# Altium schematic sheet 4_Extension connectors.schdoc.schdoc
size 309 x 223 mm; Symbol: Artery_A4; Device: Artery_A4; Company: Artery Technology; Version: 1.1; Page Size: A4; @Project Name: AT-START-F423 V1.1; @Page Count: 4; @Update Date: 2024-04-30; @Create Date: 2023-04-24; @Schematic Name: AT-START-F423 V1.1; @Page No: 4; @Page Name: Extension connectors
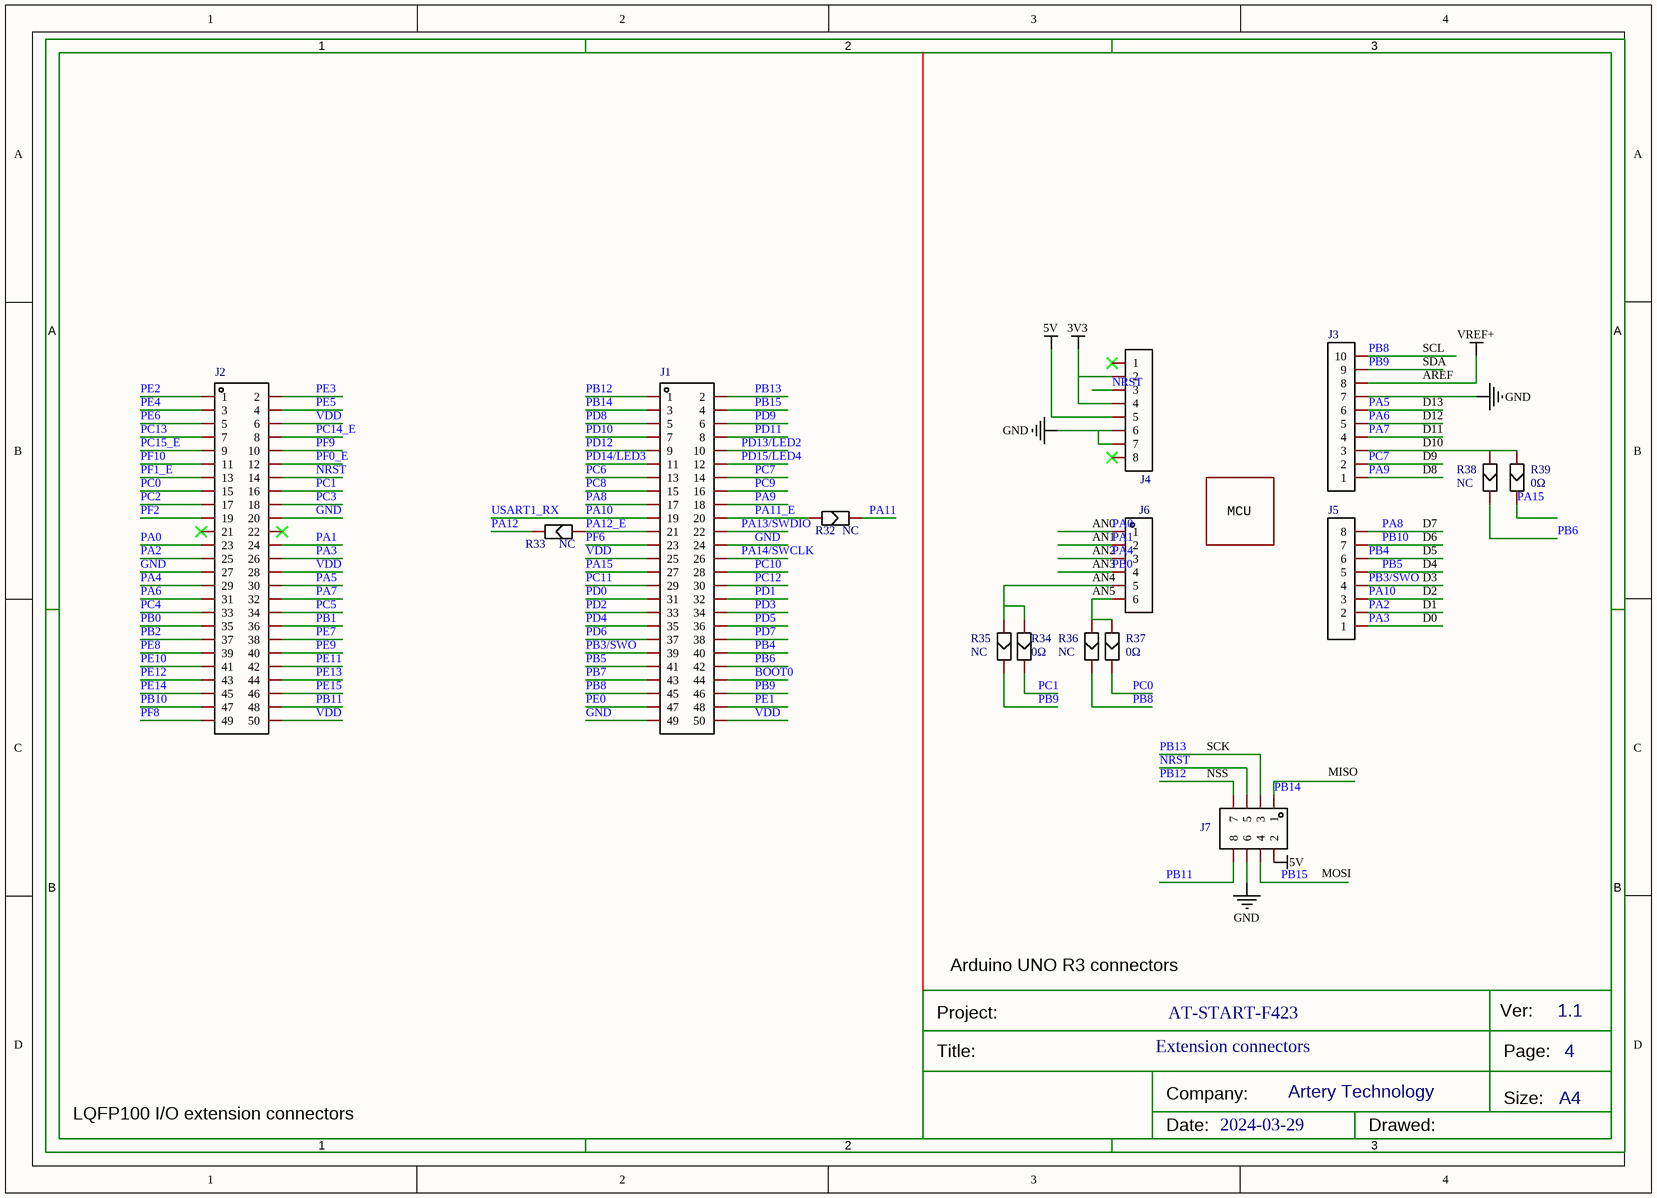
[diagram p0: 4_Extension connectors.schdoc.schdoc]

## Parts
J1  X6521WV-2x25H-C30D60  [HDR-TH_50P-2.54-V-M-R2-C25-S2.54]  (value not drawn)
J2  X6521WV-2x25H-C30D60  [HDR-TH_50P-2.54-V-M-R2-C25-S2.54]  (value not drawn)
J3  2.54-1*10P母  [AT-START-Connector 1x10]  (value not drawn)
J4  2.54-1*8P母环保  [AT-START-Connector 1x8]  (value not drawn)
J5  2.54-1*8P母环保  [AT-START-Connector 1x8]  (value not drawn)
J6  2.54-1*6P母  [AT-START-Connector 1x6]  (value not drawn)
J7  Header 4X2  [HDR2X4]  (value not drawn)
R32  NC  [SB-PAD]
R33  NC  [SB-PAD]
R34  0Ω  [SB-PAD]
R35  NC  [SB-PAD]
R36  NC  [SB-PAD]
R37  0Ω  [SB-PAD]
R38  NC  [SB-PAD]
R39  0Ω  [SB-PAD]

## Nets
3V3: J4.2 J4.4
5V: J4.5 J7.2
GND: J1.24 J1.49 J2.20 J2.27 J3.7 J4.6 J4.7 J7.6
VREF+: J3.8
BOOT0: J1.44
NRST: J2.14 J4.3 J7.5
PA0: J2.23 J6.1
PA1: J2.24 J6.2
PA2: J2.25 J5.2
PA3: J2.26 J5.1
PA4: J2.29 J6.3
PA5: J2.30 J3.6
PA6: J2.31 J3.5
PA7: J2.32 J3.4
PA8: J1.17 J5.8
PA9: J1.18 J3.1
PA10: J1.19 J5.3  [also labelled USART1_RX]
PA11: R32.2
PA11_E: J1.20 R32.1
PA12: R33.2
PA12_E: J1.21 R33.1
PA13/SWDIO: J1.22
PA14/SWCLK: J1.26
PA15: J1.27 R39.2
PB0: J2.35 J6.4
PB1: J2.36
PB2: J2.37
PB3/SWO: J1.39 J5.4
PB4: J1.40 J5.6
PB5: J1.41 J5.5
PB6: J1.42 R38.2
PB7: J1.43
PB8: J1.45 J3.10 R36.2
PB9: J1.46 J3.9 R35.2
PB10: J2.47 J5.7
PB11: J2.48 J7.8
PB12: J1.1 J7.7
PB13: J1.2 J7.3
PB14: J1.3 J7.1
PB15: J1.4 J7.4
PC0: J2.15 R37.2
PC1: J2.16 R34.2
PC2: J2.17
PC3: J2.18
PC4: J2.33
PC5: J2.34
PC6: J1.13
PC7: J1.14 J3.2
PC8: J1.15
PC9: J1.16
PC10: J1.28
PC11: J1.29
PC12: J1.30
PC13: J2.7
PC14_E: J2.8
PC15_E: J2.9
PD0: J1.31
PD1: J1.32
PD2: J1.33
PD3: J1.34
PD4: J1.35
PD5: J1.36
PD6: J1.37
PD7: J1.38
PD8: J1.5
PD9: J1.6
PD10: J1.7
PD11: J1.8
PD12: J1.9
PD13/LED2: J1.10
PD14/LED3: J1.11
PD15/LED4: J1.12
PE0: J1.47
PE1: J1.48
PE2: J2.1
PE3: J2.2
PE4: J2.3
PE5: J2.4
PE6: J2.5
PE7: J2.38
PE8: J2.39
PE9: J2.40
PE10: J2.41
PE11: J2.42
PE12: J2.43
PE13: J2.44
PE14: J2.45
PE15: J2.46
PF0_E: J2.12
PF1_E: J2.13
PF2: J2.19
PF6: J1.23
PF8: J2.49
PF9: J2.10
PF10: J2.11
VDD: J1.25 J1.50 J2.6 J2.28 J2.50
NetJ3_3: J3.3 R38.1 R39.1
NetJ6_5: J6.5 R34.1 R35.1
NetJ6_6: J6.6 R36.1 R37.1

Not connected (* = marked no-connect by the designer): J2 21* 22*; J4 1* 8*

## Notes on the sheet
- SCL
- SDA
- AREF
- D13
- D8
- D9
- D10
- D11
- D12
- (near J6) AN0
- (near J6) AN1
- MCU
- D6
- D7
- (near J6) AN2
- (near J6) AN3
- (near J6) AN4
- (near J6) AN5
- D1
- D2
- D3
- D4
- D5
- D0
- SCK
- (near J7) NSS
- MISO
- (near J7) MOSI
- Arduino UNO R3 connectors
- AT-START-F423
- Extension connectors
- LQFP100 I/O extension connectors
- 2024-03-29

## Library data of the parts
J1 J2 = X6521WV-2x25H-C30D60: 间距:2.54mm;总PIN位数:50;排数:2;插针结构:2x25P;行距:2.54mm;安装类型:直插;圆针/方针:方针;额定电流:3A;额定电压:250V;配合针长度:6mm;塑高:2.5mm;端接针长度:3mm;触头材质:黄铜;触头镀层:金;工作温度范围:-40~+105;焊接温度(最大值):260;颜色:黑色;; Manufacturer: XKB Connectivity(中国星坤); Symbol: X6521WV-2×25H-C30D60; Add into BOM: yes; Pitch: 2.54mm; Pin Structure: 2x25P; Circluar Pins/Square Pins: 方针; Current Rating (Max): 3A; Voltage Rating (Max): 250V; Welding Temperature (Max): 260
J3 = 2.54-1*10P母: Manufacturer: BOOMELE(博穆精密); Symbol: Header-Female-2.54_1x10; Add into BOM: yes; Pitch: 2.54mm; Number of Holes: 10; Holes Structure: 1x10P; Description: 间距:2.54mm;总孔位数:10;排数:1;插孔结构:1x10P;行距:-;安装类型:直插;塑高:-;触头材质:-;触头镀层:-;
J4 J5 = 2.54-1*8P母环保: Manufacturer: BOOMELE(博穆精密); Symbol: Header-Female-2.54_1x8; Add into BOM: yes; Pitch: 2.54mm; Number of Holes: 8; Holes Structure: 1x8P; Description: 间距:2.54mm;总孔位数:8;排数:1;插孔结构:1x8P;行距:-;安装类型:直插;塑高:-;触头材质:-;触头镀层:-;
J6 = 2.54-1*6P母: Manufacturer: BOOMELE(博穆精密); Symbol: Header-Female-2.54_1x6; Add into BOM: yes; Pitch: 2.54mm; Number of Holes: 6; Holes Structure: 1x6P; Description: 间距:2.54mm;总孔位数:6;排数:1;插孔结构:1x6P;行距:-;安装类型:直插;塑高:-;触头材质:-;触头镀层:-;
J7 = Header 4X2: Convert to PCB: yes
R32 R33 R35 R36 R38 = NC_SB-PAD: Convert to PCB: yes
R34 R37 R39 = NC_SB-PAD: Symbol: NC; Convert to PCB: yes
